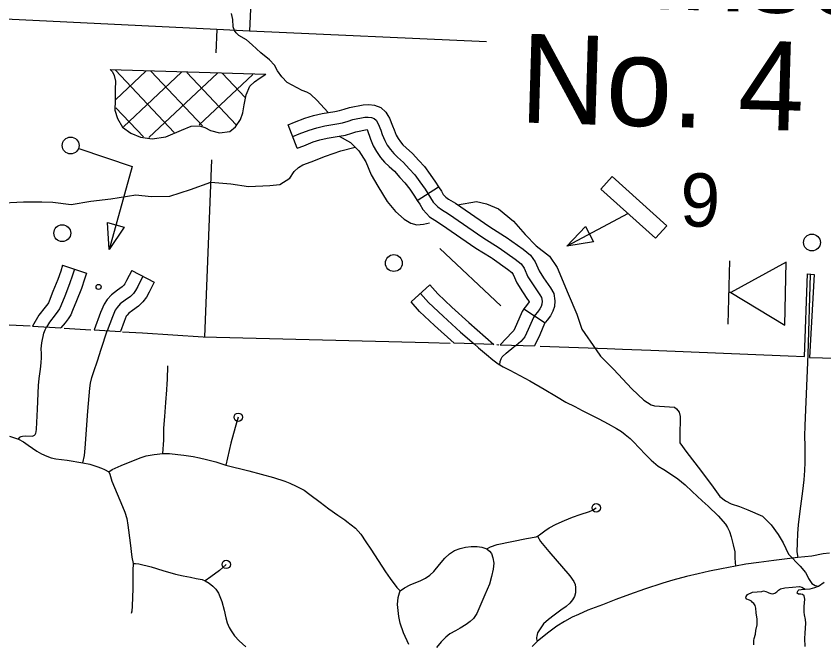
# Model space of a CAD drawing. Extents: x 653372 to 905732, y 627442 to 787275.
# Drawn here: x 692994 to 697790, y 738593 to 742323 of the extents above; entities that cross this region are included whole.
import ezdxf

# ---------------------------------------------------------------- set-up
doc = ezdxf.new("R2010")
doc.units = 0
for name, color, linetype in [('31', 7, 'Continuous'), ('32', 7, 'Continuous'), ('33', 7, 'Continuous'), ('34', 7, 'Continuous'), ('35', 7, 'Continuous'), ('4', 7, 'Continuous'), ('45', 7, 'Continuous'), ('5', 7, 'Continuous'), ('56', 7, 'Continuous'), ('57', 7, 'Continuous'), ('6', 7, 'Continuous'), ('63', 7, 'Continuous')]:
    doc.layers.add(name, color=color, linetype=linetype)

msp = doc.modelspace()

# ---------------------------------------------------------------- linework, layer by layer
at = {"layer": '31'}
for q in [(695449.8, 740725.8), (695338.6, 740625.1)]:
    msp.add_line((695338.6, 740625.1), q, dxfattribs=at)
for points in [[(695449.8, 740725.8), (695496.7, 740674), (695580.7, 740594.5), (695682.4, 740501.9), (695831, 740371.7)], [(695394.2, 740675.4), (695443, 740621.5), (695529.7, 740539.6), (695632.4, 740446), (695712.5, 740375.8)], [(695831, 740371.7), (695594.4, 740379.2), (695478.7, 740484.6), (695389.4, 740569), (695338.6, 740625.1)]]:
    msp.add_lwpolyline(points, dxfattribs=at)
at = {"layer": '32'}
for p, q in [((693269.4, 740842.6), (693411.9, 740795.8)), ((693679.9, 740811.6), (693813.5, 740743.4))]:
    msp.add_line(p, q, dxfattribs=at)
for points in [[(693269.4, 740842.6), (693258.2, 740808.4), (693240.4, 740757.9), (693212.4, 740686.6), (693188.9, 740629.1), (693185, 740618.9), (693181.5, 740614.1), (693165.8, 740594.1), (693129.1, 740546.6), (693091.3, 740481.3), (693259.8, 740470.4)], [(693340.7, 740819.2), (693329.2, 740784.2), (693310.7, 740731.7), (693282, 740658.7), (693258.6, 740601.5), (693251.7, 740583.3), (693241.6, 740569.1), (693224.9, 740547.9), (693191.5, 740504.7), (693174.7, 740475.6)], [(693679.9, 740811.6), (693649.3, 740751.8), (693639.4, 740732.7), (693633, 740724.1), (693624.2, 740715.5), (693595.8, 740695.6), (693560.3, 740667.9), (693534.7, 740639.4), (693515.4, 740612.3), (693495.3, 740562.8), (693456.1, 740458.6), (693612.6, 740448.8)], [(693411.9, 740795.8), (693400.2, 740760.1), (693381, 740705.6), (693351.6, 740630.8), (693328.4, 740573.9), (693318.3, 740547.6), (693301.6, 740524.1), (693284, 740501.7), (693259.8, 740470.4)], [(693746.7, 740777.5), (693715.9, 740717.4), (693703.2, 740692.8), (693689.8, 740674.8), (693672.4, 740657.6), (693640.4, 740635.3), (693611.6, 740612.8), (693593.3, 740592.5), (693581.6, 740576), (693565.1, 740535.5), (693534.4, 740453.8)], [(693813.5, 740743.4), (693782.6, 740683), (693766.9, 740652.9), (693746.6, 740625.4), (693720.5, 740599.7), (693684.9, 740574.9), (693662.9, 740557.7), (693652, 740545.5), (693647.8, 740539.6), (693634.9, 740508.1), (693612.6, 740448.8)]]:
    msp.add_lwpolyline(points, dxfattribs=at)
at = {"layer": '33'}
for points in [[(693389.4, 739669), (693398.6, 739711.8), (693403.8, 739755.3), (693419.2, 739975.8), (693431.7, 740112.1), (693435.5, 740142.4), (693443.8, 740175), (693454.7, 740211.9), (693475.8, 740275.9), (693497.9, 740343.4), (693534.4, 740453.8)], [(695712.5, 740375.8), (695740.1, 740351.7), (695786.9, 740312.3), (695824.5, 740281.4), (695856.9, 740257.3), (695865.2, 740252), (695885.2, 740239.6), (695924.5, 740219.7), (695984.1, 740187.1), (696043.1, 740155.8), (696130, 740105.6), (696201.8, 740062.6), (696257.5, 740029.6), (696310.6, 740003.5), (696354.4, 739979.6), (696453.4, 739929.5), (696508.8, 739900.9), (696558.6, 739872.8), (696587.9, 739854.2), (696610.9, 739836.2), (696640.5, 739813.6), (696659.6, 739793.3), (696692.7, 739758.2), (696730.9, 739717.6), (696764.5, 739684.9), (696806.7, 739649.9), (696838.8, 739628.3), (696872.7, 739607.1), (696921.9, 739574.7), (696966, 739537.8), (697008.1, 739497.6), (697066.5, 739443.9), (697102.6, 739411.6), (697162.4, 739354.5), (697206.6, 739304.6), (697217.6, 739285.5), (697228.8, 739260.6), (697239.8, 739228.3), (697251.9, 739181.3), (697260.3, 739140.7), (697261.1, 739102.7), (697265.4, 739054)], [(694312.4, 739939.6), (694293.9, 739877.8), (694268.3, 739784.8), (694238.5, 739655.3)], [(692954.3, 739826.7), (693007.8, 739810), (693036.5, 739794.3), (693065.3, 739774.7), (693116, 739738.6), (693144.3, 739723.1), (693175.3, 739708.4), (693201.9, 739698), (693230.1, 739692.6), (693296.3, 739684.5), (693389.4, 739669), (693430.6, 739660.4), (693472.3, 739647.5), (693501.4, 739637.5), (693519, 739629.8), (693543.4, 739615.9)], [(693543.4, 739615.9), (693563.1, 739628.7), (693617.5, 739652.3), (693731.1, 739698.9), (693766.6, 739709.6), (693813.8, 739719.3), (693863.9, 739724.5), (693904, 739724), (693954.7, 739718.7), (693989, 739715), (694045.2, 739707.1), (694083.1, 739698.8), (694124.1, 739689.6), (694178.6, 739673.8), (694238.5, 739655.3)], [(694238.5, 739655.3), (694375.6, 739620.6), (694522.1, 739582), (694589.8, 739560.3), (694619.3, 739547.5), (694657.2, 739531), (694703.4, 739505.7), (694738.4, 739479.9), (694798.6, 739435.4), (694851.1, 739395.4), (694904.2, 739357.4), (694945.2, 739330.6), (694956.9, 739320.7), (695008.6, 739280.9), (695040.8, 739244), (695069.3, 739199.6), (695099.6, 739155.2), (695186, 739021.1), (695213.8, 738981), (695253.6, 738927.6), (695274.4, 738909)], [(693543.4, 739615.9), (693550.5, 739600.7), (693562, 739560.8), (693593.9, 739485.5), (693625.8, 739408.8), (693639.5, 739376.2), (693650.4, 739337.7), (693656.6, 739298.7), (693671.5, 739192.9), (693681, 739108.2), (693688, 739070.5), (693687.4, 739029.6), (693686.2, 738921.8), (693683, 738816.7), (693681.5, 738787.4), (693677, 738773.5)], [(695787.8, 739157.5), (695810.4, 739170.2), (695849.2, 739183.5), (696023.6, 739220.1), (696081, 739229.5), (696088.5, 739232.7), (696101.9, 739241.7), (696133.3, 739265.5), (696159.4, 739282.7), (696200.2, 739303.6), (696250.4, 739326.9), (696297.1, 739346), (696342.5, 739361.7), (696398.5, 739379.7), (696416.7, 739386.8), (696438.5, 739401.5)], [(696088.5, 739232.7), (696106.4, 739201.4), (696156.7, 739142.7), (696281.2, 738996.4), (696304.9, 738963.2), (696313, 738946.8), (696315.8, 738927.9), (696315.8, 738897.1), (696308.3, 738875.2), (696297.4, 738855), (696282.3, 738835.2), (696260.4, 738815.3), (696228.1, 738792.4), (696188.8, 738763.7), (696154.8, 738737.4), (696124.5, 738711.7), (696104.9, 738682.4), (696090.1, 738658.5), (696084.8, 738639), (696083.3, 738630.5), (696084.3, 738622.4), (696088.1, 738607.3)], [(695274.4, 738909), (695298.8, 738926.2), (695333.5, 738944.8), (695396.6, 738969.4), (695425.2, 738983.1), (695450.5, 739001.1), (695473.3, 739022.6), (695507.8, 739064.3), (695539.7, 739102.6), (695567.8, 739128.2), (695597.4, 739147.8), (695631, 739159.6), (695662, 739167.2), (695696, 739171.3), (695731, 739171.1), (695758.2, 739168.6), (695787.8, 739157.5), (695805.3, 739144.1), (695816, 739129.3), (695824.6, 739103.4), (695829.7, 739073.4), (695826.9, 739037.6), (695816.1, 738992.7), (695803.7, 738948.6), (695776.2, 738884.6), (695728.5, 738774.2), (695709.6, 738743.1), (695690.3, 738725.8), (695665.9, 738707.7), (695630.2, 738686.6), (695601.6, 738671.2), (695569.5, 738651.9), (695545.9, 738633.8), (695517.7, 738604.8), (695489.4, 738571.5)], [(697823.1, 739132.4), (697785.9, 739127.2), (697718.4, 739114.8), (697635, 739105.5), (697493.6, 739089), (697403.8, 739076.3), (697325.8, 739066.9), (697265.4, 739054), (697182.3, 739039.6), (697110.5, 739025.5), (697044.1, 739009.4), (696974.6, 738993.5), (696892.6, 738970.6), (696833.4, 738954.3), (696724.8, 738917.8), (696635.4, 738887.1), (696555, 738856.1), (696474.5, 738825.2), (696387.8, 738792.5), (696333.7, 738767), (696295.8, 738751.1), (696249, 738725.4), (696203.9, 738698.7), (696149.4, 738657.1), (696088.1, 738607.3), (696057.5, 738576.8)], [(693688, 739070.5), (693702, 739070.2), (693721.4, 739068.3), (693796.2, 739050), (693863.9, 739029.9), (693939.6, 739008.2), (693986.2, 738997.4), (694028.8, 738990.1), (694062.1, 738982.4), (694098.7, 738974.6), (694116.5, 738967.3), (694140.2, 738953.9), (694161.8, 738936.5), (694178.7, 738917.2), (694194.7, 738894), (694204.1, 738873.6), (694215.3, 738845.1), (694228.5, 738793.8), (694239.2, 738747.2), (694247, 738718.9), (694258.9, 738691), (694269.7, 738671.3), (694290.3, 738641.2), (694318.8, 738610.9), (694358.4, 738576.1)], [(694241.4, 739065.4), (694200.8, 739029.7), (694150.1, 738991.7), (694116.5, 738967.3)], [(695326, 738589.2), (695293.1, 738659.3), (695274.3, 738715.4), (695265.3, 738754.9), (695258.9, 738826.8), (695262.7, 738869.4), (695270.4, 738896.5), (695274.4, 738909)]]:
    msp.add_lwpolyline(points, dxfattribs=at)
for centre in [(694312.4, 739939.6), (696438.5, 739401.5), (694241.4, 739065.4)]:
    msp.add_circle(centre, 25, dxfattribs=at)
at = {"layer": '34'}
for points in [[(697707.6, 740787.2), (697694.1, 740312.9), (697676.9, 739890.4), (697675.1, 739827.8), (697677.1, 739770.4), (697676.8, 739712.2), (697677.8, 739670.5), (697675.6, 739622.8), (697670.2, 739567.8), (697662.2, 739499.5), (697647.5, 739381.5), (697637.6, 739299.5), (697633.8, 739248.2), (697632.2, 739193.1), (697629.1, 739139.5), (697635, 739105.5)], [(693007.8, 739810), (693016.4, 739820.4), (693024, 739825.8), (693031, 739827.9), (693047.7, 739829.2), (693088.8, 739827.5), (693095.3, 739828.7), (693101.9, 739832.7), (693106.2, 739838.1), (693110.6, 739845.8), (693111.8, 739853.7), (693114.6, 739868.4), (693120.9, 739987.2), (693126.5, 740128.3), (693131, 740170.3), (693138.7, 740224.7), (693143.1, 740263), (693143.5, 740294), (693143.3, 740318.4), (693142.3, 740347.1), (693143.3, 740364.2), (693146.6, 740382.2), (693150, 740402.4), (693153.8, 740419.4), (693159, 740439.6), (693166.5, 740458.4), (693174.7, 740475.6)], [(695865.2, 740252), (695867.8, 740270.9), (695872.8, 740286.5), (695879.7, 740298.7), (695902.7, 740320.3), (695949.7, 740357.6), (695962.4, 740367)], [(693863.9, 739724.5), (693870, 739803.3), (693870.4, 739874.9), (693875.9, 739943.9), (693881.8, 740028), (693888.2, 740101.9), (693890.1, 740139), (693892.6, 740165), (693894.2, 740245)]]:
    msp.add_lwpolyline(points, dxfattribs=at)
at = {"layer": '35'}
for points in [[(694845.2, 741753.4), (694781.9, 741822.9), (694742.4, 741859), (694720.3, 741870.9), (694691.3, 741881.9), (694661.4, 741897.5), (694603.8, 741929.6), (694572.1, 741962.1), (694545, 741999), (694526.9, 742032.2), (694497.4, 742063.5), (694445.8, 742105.6), (694395.4, 742153.3), (694361.3, 742182.5), (694316, 742208.6), (694300.7, 742224.9), (694290.1, 742237.4), (694282.9, 742260.1), (694279.7, 742304.2), (694272.9, 742338.2)], [(694912.6, 741609.7), (694978.7, 741572.4), (695029.1, 741522.8), (695069.5, 741458.1), (695101.8, 741380.2), (695142.1, 741313.6), (695197, 741221.5), (695247.2, 741162.3), (695297.7, 741116.5), (695337.4, 741092.3), (695373.6, 741083.5), (695412.2, 741086.2), (695447.3, 741095.6)], [(694374, 741311.6), (694499.1, 741317.5), (694559, 741322.5), (694619.2, 741361.4), (694644.3, 741400), (694670.3, 741423.2), (694696, 741439.3), (694745.2, 741457.5), (694830.5, 741491.4), (694921.4, 741522.5), (695006.6, 741545)], [(693704.6, 741260.6), (693795.4, 741251.5), (693906.5, 741253.8), (694028.5, 741292.3), (694150.7, 741336.5), (694268.7, 741327.6), (694374, 741311.6)], [(691845.2, 741323.3), (691994.1, 741306), (692037.4, 741298), (692152.5, 741248.2), (692280.1, 741190.9), (692325.7, 741164.2), (692362, 741157.5), (692397.2, 741159.3), (692418.5, 741168.5), (692439.5, 741166.4), (692492.8, 741162), (692582.3, 741172.9), (692637, 741171.2), (692673.4, 741173.4), (692716.9, 741184.8), (692789.1, 741202.3), (692879.3, 741210.9), (693036.9, 741220.2), (693145.5, 741220.2), (693211.5, 741217.8), (693320.8, 741204.6), (693438, 741223.6), (693556.4, 741238.3), (693704.6, 741260.6)], [(695614.3, 741202.8), (695727.7, 741220.9), (695786.9, 741207.6), (695857.2, 741178.6), (695947.3, 741104.7), (696016.1, 741025.7), (696081.4, 740958.3), (696160.3, 740896.3), (696206.3, 740829.7), (696270.9, 740673.8), (696322.1, 740552), (696353.5, 740462.4), (696437.1, 740339.4)], [(696437.1, 740339.4), (696464.1, 740302.1), (696540.7, 740224.8), (696650.6, 740108), (696721.7, 740040.4), (696764.1, 740012.7), (696784.2, 740008.2), (696843.6, 740003.6), (696903.1, 739998.9), (696915.3, 739989.9), (696931.1, 739969.2), (696936.1, 739945), (696934.4, 739825.8), (696935.2, 739787.3), (696975.8, 739729.3), (697057.3, 739624.9), (697133.1, 739524.5), (697172.8, 739469.6), (697205.6, 739442.6), (697238.8, 739425.3), (697289.3, 739409.4), (697338.6, 739388.6), (697424.9, 739352.7), (697477.2, 739301.1), (697517.7, 739243.1), (697548.9, 739194.1), (697580.5, 739125.8), (697649.3, 739053.8), (697680, 739016.4), (697691, 738999.7), (697698.1, 738981.2), (697719.4, 738951.7), (697737.3, 738940.6), (697758.9, 738936.7)], [(697420.7, 738904.6), (697432.3, 738907.4), (697445.7, 738905), (697455.1, 738899.6), (697462.7, 738895.5), (697475.4, 738891.9), (697487.6, 738890.3), (697498.6, 738893.8), (697510.4, 738902.4), (697519.7, 738912.4), (697532.8, 738921), (697558, 738925.4), (697602.7, 738930.5), (697645.2, 738934.4), (697659.8, 738930.1), (697669.3, 738924), (697679.4, 738918.6), (697707.6, 738919.6), (697736.8, 738927.1), (697758.9, 738936.7), (697791, 738960.1)], [(697373.3, 738587.9), (697373.4, 738612.9), (697375.1, 738625.7), (697383.5, 738650.1), (697386.7, 738671.8), (697392.9, 738706.3), (697393.3, 738739.7), (697388.6, 738777.7), (697386.9, 738805.4), (697382.3, 738821.6), (697373.6, 738832.7), (697366.7, 738838.7), (697359.3, 738846.6), (697347.9, 738852.1), (697341.5, 738854.9), (697331.6, 738858.8), (697327.3, 738866.6), (697328.8, 738874.6), (697336.7, 738886.5), (697365.7, 738899.5), (697420.7, 738904.6)], [(697679, 738577.3), (697677.4, 738624.1), (697678.4, 738657.6), (697681.3, 738687), (697683.2, 738716.4), (697680.8, 738737.8), (697675.5, 738765.4), (697673.9, 738780.8), (697672.9, 738814.2), (697676.3, 738857.8), (697673.8, 738877.8), (697662.4, 738886.8), (697653.8, 738888.1), (697639.6, 738887.5), (697631.1, 738893.8), (697632.4, 738902.9), (697637.2, 738910.9), (697641.9, 738914.3), (697655.6, 738916), (697679.4, 738918.6)]]:
    msp.add_lwpolyline(points, dxfattribs=at)
at = {"layer": '4'}
msp.add_lwpolyline([(695785.8, 742171.2), (694378.4, 742234.8)], dxfattribs=at)
at = {"layer": '45'}
for p, q in [((694663, 741538.1), (694608.6, 741677.9)), ((695375.5, 741228.4), (695501.5, 741309.7)), ((696009.2, 740584), (696134.5, 740501.6))]:
    msp.add_line(p, q, dxfattribs=at)
for points in [[(694608.6, 741677.9), (694647.4, 741692.9), (694707.9, 741717.2), (694758.7, 741732.5), (694811.7, 741745.3), (694885.5, 741757.3), (694913.8, 741762.5), (694942.3, 741771.4), (694974, 741780.9), (695054.7, 741797.1), (695087.2, 741798.2), (695121.8, 741793.8), (695158.6, 741780.3), (695188.9, 741753.5), (695201, 741733.5)], [(694635.8, 741608), (694675, 741623.2), (694732.7, 741646.4), (694778.3, 741660.1), (694826.5, 741671.8), (694898.3, 741683.4), (694931.9, 741689.6), (694964.4, 741699.8), (694992.1, 741708.1), (695063.4, 741722.4), (695083.7, 741723.1), (695104, 741720.5), (695119.5, 741714.8), (695130.6, 741704.9)], [(695201, 741733.5), (695210.4, 741717.9), (695229, 741671.9), (695238, 741647.1), (695250.9, 741616.2), (695261.4, 741595.6), (695275.1, 741576.1), (695289.4, 741559.4), (695309, 741541.5), (695346.9, 741507.1), (695383.9, 741465.5), (695417.7, 741428.9), (695452.6, 741382.9), (695484.3, 741336.4), (695501.5, 741309.7)], [(695130.6, 741704.9), (695143.1, 741684.2), (695159, 741645.1), (695168.1, 741619.9), (695182.7, 741584.7), (695197, 741556.8), (695215.8, 741530), (695235.5, 741507.1), (695258.4, 741486.1), (695293.5, 741454.2), (695328.4, 741415.1), (695360.2, 741380.7), (695391.7, 741339.1), (695421.8, 741294.9), (695454.8, 741243.9), (695469.1, 741218.6), (695483.7, 741203), (695497, 741189.5), (695520.2, 741173.7), (695561.4, 741148.2), (695764.7, 741007.7), (695861.8, 740947.1), (695957.5, 740880), (695992, 740850.7), (696010.3, 740825.7), (696032.3, 740774.5), (696063, 740726.4), (696091.2, 740684.2), (696103.9, 740668.1), (696113.2, 740650.8), (696116.4, 740628.7), (696115.3, 740611), (696111.6, 740598), (696104, 740583.8), (696089, 740564.6), (696076, 740549.2), (696065, 740532.5), (696034, 740460.7), (696013.7, 740416.7), (696004.9, 740405.1), (695991.3, 740390.5), (695962.4, 740367)], [(694663, 741538.1), (694702.5, 741553.4), (694757.5, 741575.5), (694797.9, 741587.7), (694841.4, 741598.2), (694911.1, 741609.5), (694950, 741616.7), (694986.4, 741628.1), (695010.3, 741635.3), (695077.9, 741648.8)], [(695077.9, 741648.8), (695098.1, 741592.8), (695114.6, 741553.2), (695132.6, 741518), (695156.6, 741483.9), (695181.5, 741454.8), (695207.9, 741430.6), (695240.2, 741401.3), (695272.9, 741364.7), (695302.6, 741332.5), (695330.8, 741295.3), (695359.3, 741253.5), (695375.5, 741228.4)], [(695501.5, 741309.7), (695519, 741282.7), (695529.9, 741263.3), (695537.7, 741255.1), (695545.3, 741247.4), (695561.1, 741236.6), (695602.4, 741211), (695805.9, 741070.4), (695893.5, 741015.7)], [(695375.5, 741228.4), (695390.6, 741205.1), (695408.2, 741173.8), (695429.7, 741151), (695448.8, 741131.6), (695479.3, 741110.8), (695520.3, 741085.5), (695723.5, 740945), (695814.1, 740888.5)], [(695893.5, 741015.7), (695903.3, 741009.7), (696003.4, 740939.4), (696047.3, 740902.2), (696075.8, 740863.1), (696098.8, 740809.8), (696125.8, 740767.4), (696152, 740728.3), (696166.9, 740709.3), (696185.5, 740674.7), (696191.8, 740631.7), (696189.6, 740598.2), (696181.5, 740569.7), (696167, 740542.7), (696147.2, 740517.3), (696136.3, 740504.3), (696134.5, 740501.6)], [(695814.1, 740888.5), (695820.4, 740884.5), (695911.6, 740820.5), (695936.7, 740799.3), (695944.7, 740788.3), (695965.8, 740739.3), (696000.2, 740685.4), (696030.5, 740640.2), (696040.9, 740626.9), (696040.9, 740626.9), (696041.1, 740625.7), (696041, 740625.2), (696040.9, 740624.9), (696030.7, 740611.8), (696015.8, 740594.1), (696009.2, 740584)], [(696009.2, 740584), (695998.8, 740568.2), (695965.6, 740491.2), (695949.2, 740455.7), (695947.5, 740453.5), (695939.9, 740445.3), (695867.5, 740370.4), (696071.7, 740363.3)], [(696134.5, 740501.6), (696131.3, 740496.8), (696102.5, 740430.1), (696071.7, 740363.3)]]:
    msp.add_lwpolyline(points, dxfattribs=at)
at = {"layer": '5'}
for points in [[(694185, 742244.3), (694179.4, 742105.7)], [(694153.7, 741468.9), (694111.2, 740418.4)]]:
    msp.add_lwpolyline(points, dxfattribs=at)
at = {"layer": '56'}
for p, q in [((693545.2, 740936.4), (693537, 741097.5)), ((693537, 741097.5), (693635.3, 741070.1)), ((693635.3, 741070.1), (693545.2, 740936.4)), ((696263, 740955.5), (696374.1, 741072.4)), ((696374.1, 741072.4), (696422, 740982.4)), ((696422, 740982.4), (696263, 740955.5))]:
    msp.add_line(p, q, dxfattribs=at)
for points in [[(693366.3, 741537.1), (693682.5, 741429.9), (693545.2, 740936.4)], [(696627.7, 741149.7), (696263, 740955.5)], [(695510, 740943.3), (695871.4, 740602.3)]]:
    msp.add_lwpolyline(points, dxfattribs=at)
msp.add_lwpolyline([(696465.1, 741296), (696532, 741370.3), (696857.2, 741077.7), (696790.3, 741003.3)], close=True, dxfattribs=at)
for centre, radius in [((693317.2, 741554.7), 50), ((693267.5, 741033.7), 50), ((697719.2, 740978.5), 50), ((695236.7, 740855.9), 50), ((693483.1, 740714), 15)]:
    msp.add_circle(centre, radius, dxfattribs=at)
at = {"layer": '57'}
for p, q in [((693552.2, 742006.9), (694475.8, 741979.2)), ((693931.4, 741631.8), (693582.7, 742002.1)), ((693584.9, 741828.4), (693764, 741997)), ((693631.6, 741666.3), (693974.9, 741989.5)), ((693782.1, 741601.9), (694188.6, 741984.7)), ((694100.8, 741670.7), (693793.6, 741996.9)), ((694300.3, 741677.6), (694007.9, 741988.2)), ((694080.3, 741676.8), (694398.7, 741976.6)), ((694352, 741841.5), (694219.5, 741982.3)), ((693749.9, 741605.7), (693586.6, 741779.1)), ((697222.6, 740493.6), (697231, 740868.5)), ((697565.7, 740861), (697236.8, 740680.8)), ((697557.3, 740486.1), (697565.7, 740861)), ((697236.8, 740680.8), (697226.8, 740681)), ((697236.8, 740680.8), (697557.3, 740486.1))]:
    msp.add_line(p, q, dxfattribs=at)
msp.add_lwpolyline([(693552.2, 742006.9), (693564.9, 741992), (693576.7, 741969.6), (693583.9, 741936.2), (693582.5, 741886.5), (693581.9, 741821.6), (693580.1, 741763.7), (693595.3, 741714.9), (693625.5, 741664.3), (693674.1, 741626.9), (693731.4, 741603.1), (693801.6, 741594.1), (693882, 741606.8), (693975.7, 741645.4), (694033.1, 741668.6), (694081.5, 741671.3), (694114.3, 741660.6), (694146.9, 741643.1), (694200.4, 741629), (694262.8, 741638.2), (694296.7, 741664.8), (694325.7, 741709.5), (694339.3, 741749.2), (694347.6, 741795.9), (694360.5, 741854.9), (694381.4, 741908.1), (694408.4, 741932.2), (694442.3, 741957.4), (694475.8, 741979.2)], dxfattribs=at)
at = {"layer": '6'}
for points in [[(694412.9, 742988.2), (694378.4, 742234.8), (694185, 742244.3), (692846.4, 742310), (692837.3, 741488.6), (692820.6, 741157.2), (692785.5, 740496.1), (693076.5, 740482)], [(696106.1, 740362.1), (696503.1, 740348.3), (696594.5, 740345.2), (696763.2, 740338.2), (697577.2, 740304), (697675.8, 740299.8), (697693, 740792), (697732.1, 740788.5), (697705.3, 740295.3), (697858.7, 740290.9), (698098.4, 740279.3), (698090.7, 740025.7), (698086, 739868.1), (698078.3, 739608.7), (698065.8, 739304.5)], [(693277.9, 740469.3), (693437.5, 740459.7)], [(693625.7, 740448), (693744.2, 740440.4), (694105, 740418.5), (695441.3, 740383.6), (695571.2, 740379.9)], [(695848.1, 740371.1), (695859.8, 740370.6)]]:
    msp.add_lwpolyline(points, dxfattribs=at)

# ---------------------------------------------------------------- texts
at = {"layer": '56'}
msp.add_text('9', height=316.8, rotation=358.28, dxfattribs=at).set_placement((696933.3, 741075.8))
at = {"layer": '63'}
for s, p in [('Inset', (696739, 742367.1)), ('No. 4', (695980.5, 741691.9))]:
    msp.add_text(s, height=528, rotation=358.28, dxfattribs=at).set_placement(p)

doc.saveas('drawing.dxf')
